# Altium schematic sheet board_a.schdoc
size 400 x 277 mm; Device: default420x297; Symbol: default420x297; Name: default420x297; Size: "A3"; Id: /; File: board_a; Sheet: /
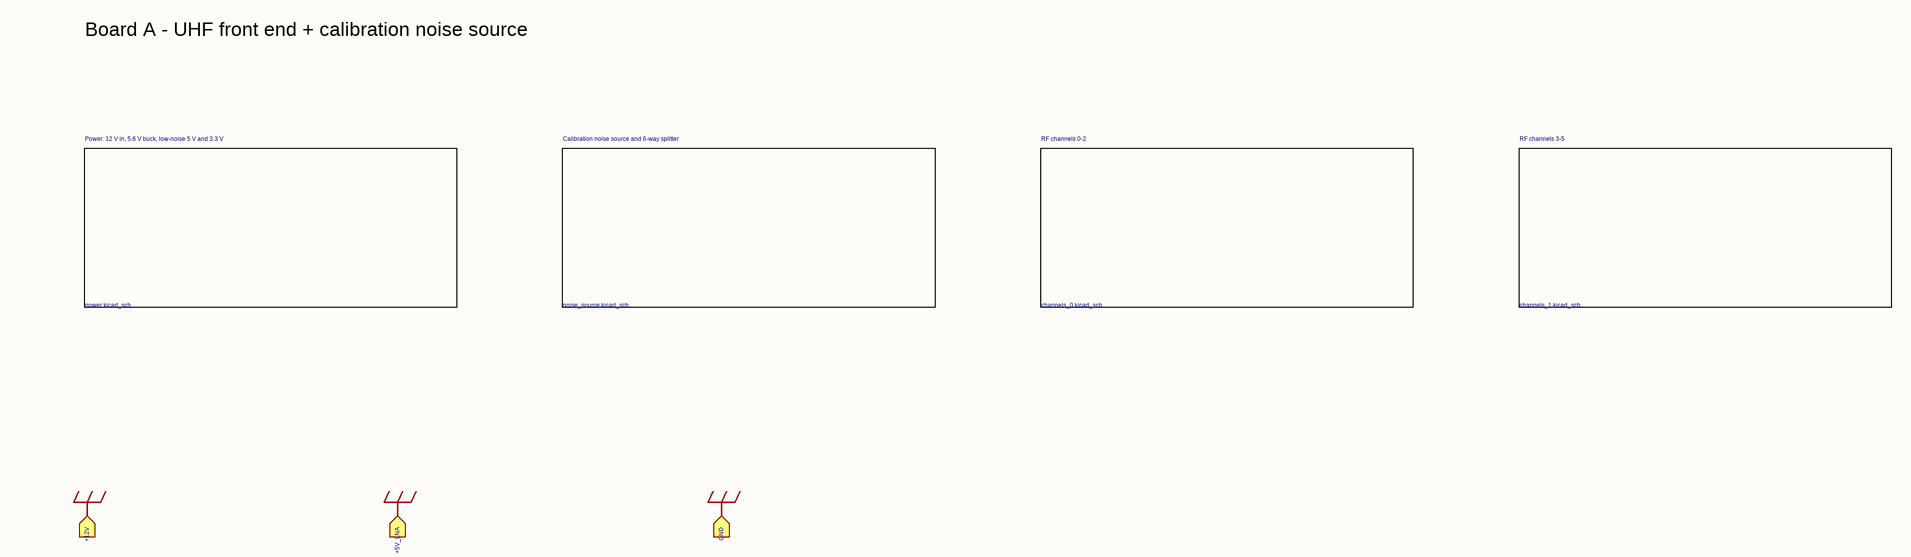
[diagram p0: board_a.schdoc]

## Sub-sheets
CBB? = power.schdoc: no entries  | Symbol: power; Sheetname: Power: 12 V in, 5.6 V buck, low-noise 5 V and 3.3 V; Sheetfile: power.kicad_sch
CBB? = noise_source.schdoc: no entries  | Symbol: noise_source; Sheetname: Calibration noise source and 6-way splitter; Sheetfile: noise_source.kicad_sch
CBB? = channels_0.schdoc: no entries  | Symbol: channels_0; Sheetname: RF channels 0-2; Sheetfile: channels_0.kicad_sch
CBB? = channels_1.schdoc: no entries  | Symbol: channels_1; Sheetname: RF channels 3-5; Sheetfile: channels_1.kicad_sch

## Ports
+5V_LNA (in), +12V (in), GND (in)

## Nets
power_PWR_FLAG: port +12V, port +5V_LNA, port GND

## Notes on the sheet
- Board A - UHF front end + calibration noise source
